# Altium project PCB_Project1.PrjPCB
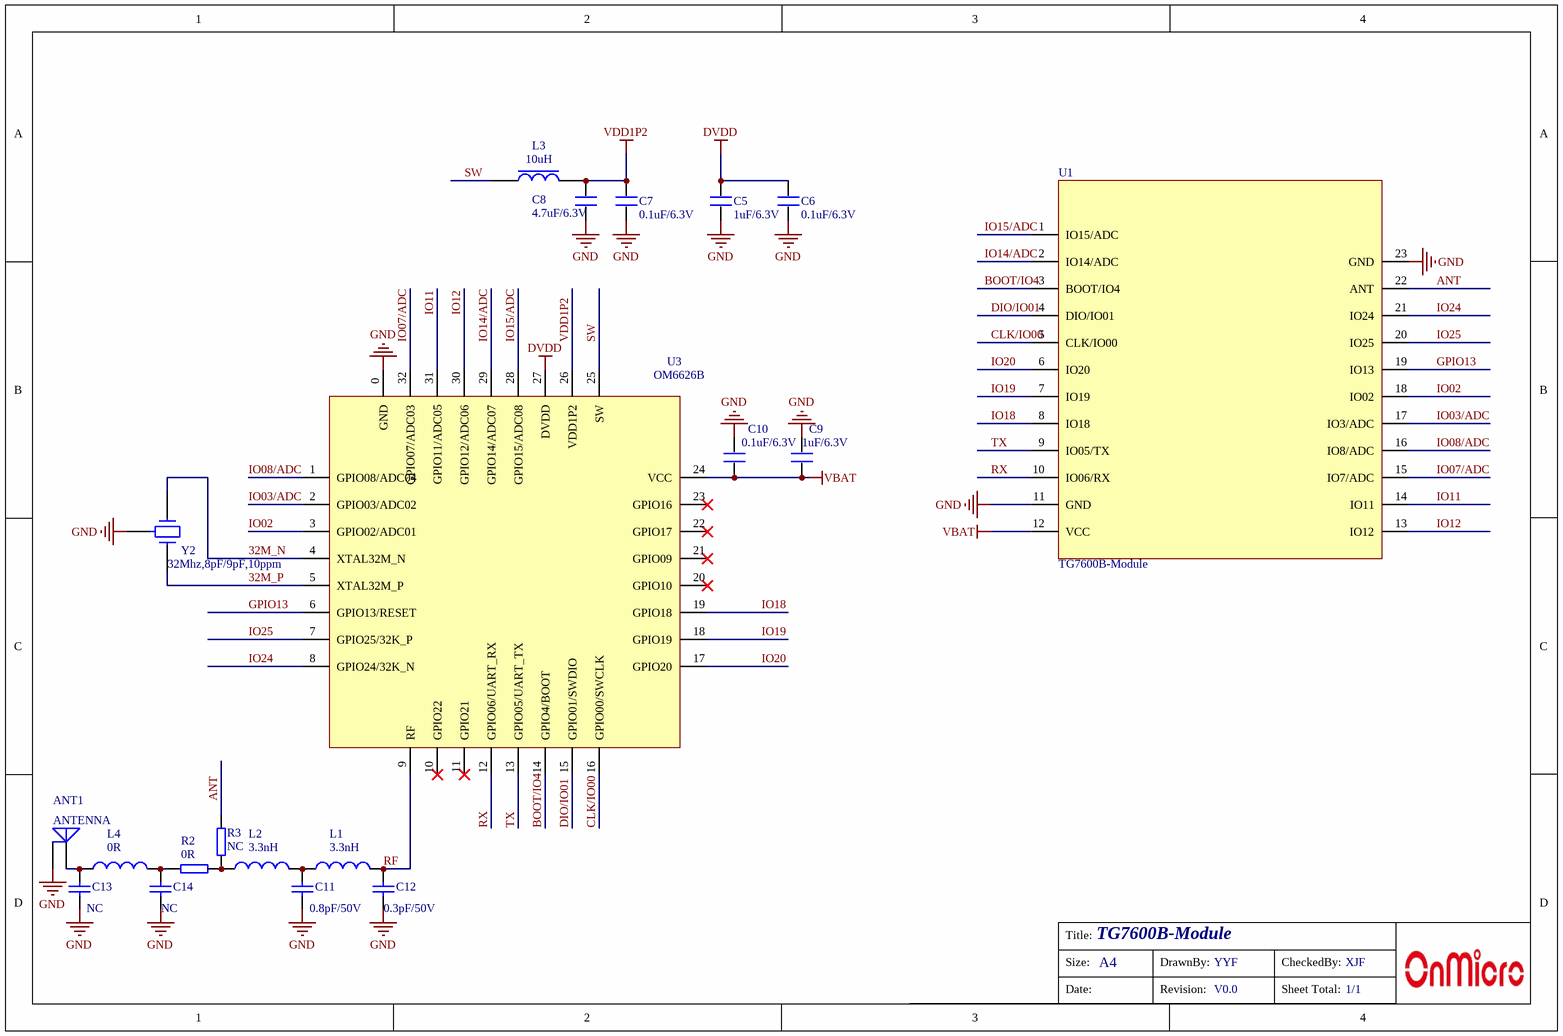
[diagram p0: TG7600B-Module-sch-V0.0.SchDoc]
1 sheet, 20 parts. Net scope: global (net labels, ports and power ports of the same name join across sheets).
Board file: TG7600B-Module-pcb-V0.0.PcbDoc

## Sheet TG7600B-Module-sch-V0.0.SchDoc: TG7600B-Module
size A4; CheckedBy: XJF; DrawnBy: YYF; Revision: V0.0; SheetTotal: 1/1; PageSetup: Record=PageOptions|CenterHorizontal=True|CenterVertical=True|PrintScale=1.00|XCorrection=1.00|YCorrection=1.00|PrintKind=0|BorderSize=5000000|LeftOffset=0|BottomOffset=0|Orientation=2|PaperLength=1000|PaperWidth=1000|Scale=100|PaperSource=7|PrintQuality=-4|MediaType=1|DitherType=10|PaperKind=A4|PrintScaleMode=1

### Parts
ANT1  ANTENNA  [2.4G PCB ANT-F-1]
C5  1uF/6.3V  [C-0201]
C6  0.1uF/6.3V  [C-0201]
C7  0.1uF/6.3V  [C-0201]
C8  4.7uF/6.3V  [C-0402]
C9  1uF/6.3V  [C-0201]
C10  0.1uF/6.3V  [C-0201]
C11  0.8pF/50V  [C-0201]
C12  0.3pF/50V  [C-0201]
C13  NC  [C-0201]
C14  NC  [C-0201]
L1  3.3nH  [R-0201-1]
L2  3.3nH  [R-0201-1]
L3  10uH  [R-0603]
L4  0R  [R-0201-1]
R2  0R  [R-0201-1]
R3  NC  [R-0201-1]
U1  TG7600B-Module
U3  OM6626B  [QFN32-4*4-0.4]
Y2  32Mhz,8pF/9pF,10ppm  [XD-2016]

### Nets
DVDD: C5.2 C6.2 U3.27(DVDD)
GND: ANT1.2 C5.1 C6.1 C7.1 C8.1 C9.2 C10.2 C11.1 C12.1 C13.1 C14.1 U1.11(GND) U1.23(GND) U3.0(GND) Y2.3
VBAT: C9.1 C10.1 U1.12(VCC) U3.24(VCC)
VDD1P2: C7.2 C8.2 L3.2 U3.26(VDD1P2)
32M_N: U3.4(XTAL32M_N) Y2.1
32M_P: U3.5(XTAL32M_P) Y2.2
ANT: R3.2 U1.22(ANT)
BOOT/IO4: U1.3(BOOT/IO4) U3.14(GPIO4/BOOT)
CLK/IO00: U1.5(CLK/IO00) U3.16(GPIO00/SWCLK)
DIO/IO01: U1.4(DIO/IO01) U3.15(GPIO01/SWDIO)
GPIO13: U1.19(IO13) U3.6(GPIO13/RESET)
IO02: U1.18(IO02) U3.3(GPIO02/ADC01)
IO03/ADC: U1.17(IO3/ADC) U3.2(GPIO03/ADC02)
IO07/ADC: U1.15(IO7/ADC) U3.32(GPIO07/ADC03)
IO08/ADC: U1.16(IO8/ADC) U3.1(GPIO08/ADC04)
IO11: U1.14(IO11) U3.31(GPIO11/ADC05)
IO12: U1.13(IO12) U3.30(GPIO12/ADC06)
IO14/ADC: U1.2(IO14/ADC) U3.29(GPIO14/ADC07)
IO15/ADC: U1.1(IO15/ADC) U3.28(GPIO15/ADC08)
IO18: U1.8(IO18) U3.19(GPIO18)
IO19: U1.7(IO19) U3.18(GPIO19)
IO20: U1.6(IO20) U3.17(GPIO20)
IO24: U1.21(IO24) U3.8(GPIO24/32K_N)
IO25: U1.20(IO25) U3.7(GPIO25/32K_P)
RF: C12.2 L1.2 U3.9(RF)
RX: U1.10(IO06/RX) U3.12(GPIO06/UART_RX)
SW: L3.1 U3.25(SW)
TX: U1.9(IO05/TX) U3.13(GPIO05/UART_TX)
NetANT1_1: ANT1.1(A) C13.2 L4.1
NetC11_2: C11.2 L1.1 L2.2
NetC14_2: C14.2 L4.2 R2.1
NetL2_1: L2.1 R2.2 R3.1

Not connected (* = marked no-connect by the designer): U3 10(GPIO22)* 11(GPIO21)* 20(GPIO10)* 21(GPIO09)* 22(GPIO17)* 23(GPIO16)*

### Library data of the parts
C5-C10 = C_1
C11 C13 = Cap: Capacitor; Value: 1.2pF
C12 C14 = Cap: Capacitor; Value: 0.5pF
L1 L2 L4 = Inductor: Code_IEC: 1005; Value: 2.7nH
L3 = INDUCTOR
R2 R3 = RES
U3 = OM6626QMHAQ
Y2 = CRYSTAL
